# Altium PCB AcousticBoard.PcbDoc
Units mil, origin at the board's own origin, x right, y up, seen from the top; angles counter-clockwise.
Board outline 6000 x 4000 mil, 2 copper layers (Top Layer, Bottom Layer); 82 components, 63 nets, 281 pads, 66 vias.
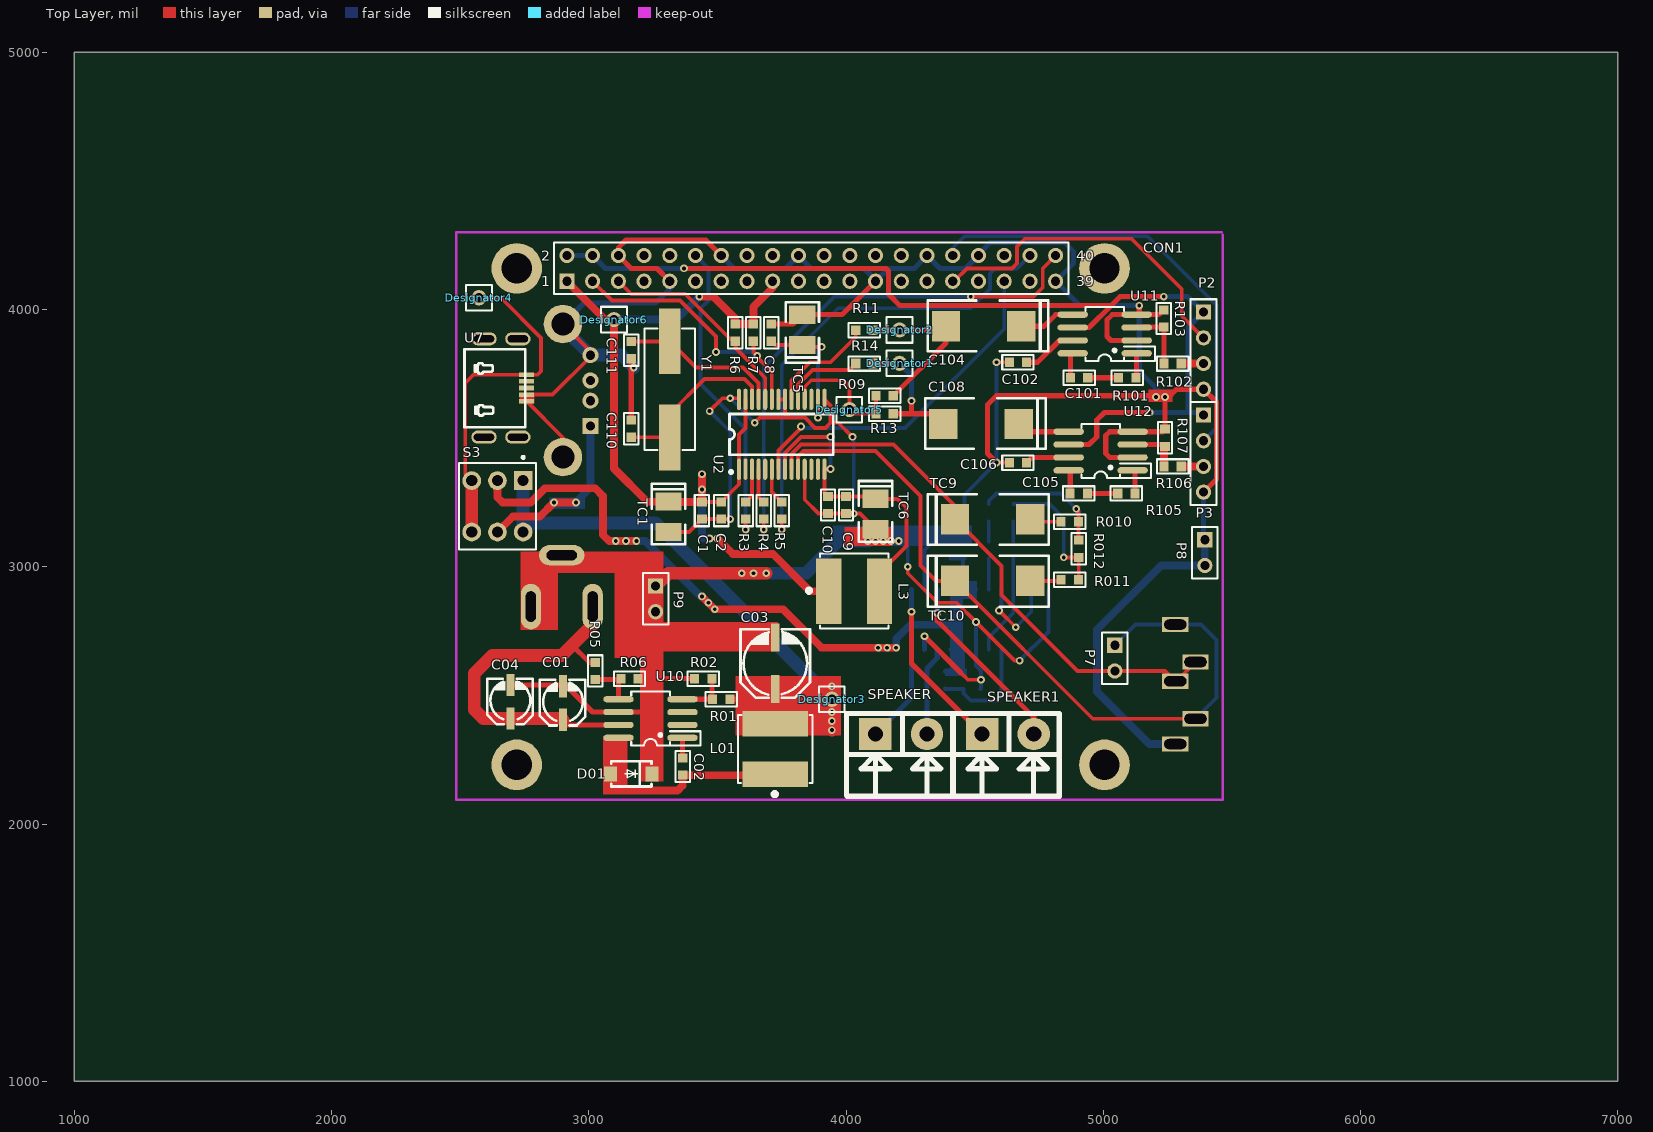
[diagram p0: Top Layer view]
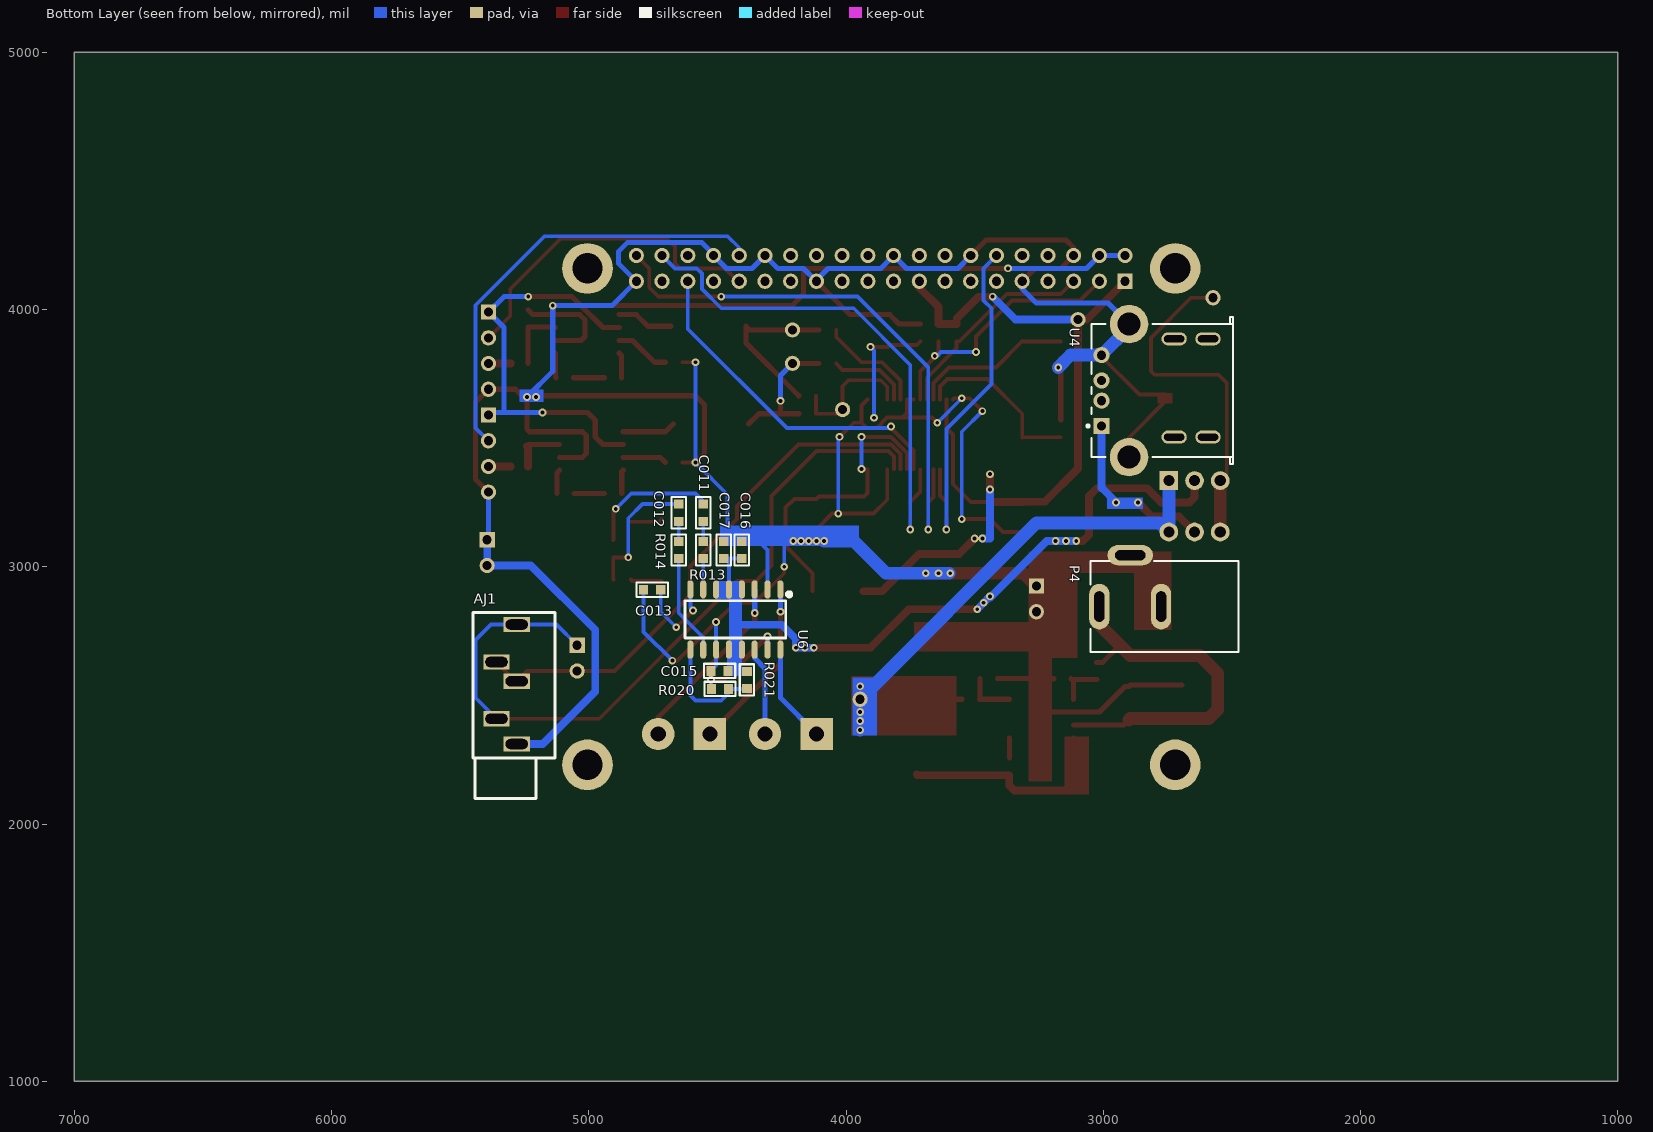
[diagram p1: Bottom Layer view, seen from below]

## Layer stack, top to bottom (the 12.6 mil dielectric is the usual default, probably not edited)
Top Solder: solder mask 0.4, Solder Resist, Dk 3.5
Top Layer: signal copper 1.4
Dielectric 1: dielectric 12.6, FR-4, Dk 4.8
Bottom Layer: signal copper 1.4
Bottom Solder: solder mask 0.4, Solder Resist, Dk 3.5

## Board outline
1000,1000 7000,1000 7000,5000 1000,5000

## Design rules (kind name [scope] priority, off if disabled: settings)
Clearance [All] p1: gap=5 ignorepadtopadclearanceinfootprint=FALSE
ComponentClearance [All] p1: gap=10 collisioncheckmode=3 verticalgap=6 showdistances=TRUE
PolygonConnect [All] p1: connectstyle=Relief reliefconductorwidth=10 reliefentries=4 polygonreliefangle="90 Angle" airgapwidth=10
RoutingVias [All] p1: holewidth=28 width=50 viastyle="Through Hole" minholewidth=10 minwidth=10 maxholewidth=50 maxwidth=100
SolderMaskExpansion [All] p1: expansion=4
Width [All] p1: maxlimit=100 minlimit=6 preferedwidth=50
29 further rules are at their usual default settings.

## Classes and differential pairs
component class MultiFcnAcousticBoard: AJ1 C1 C01 C02 C2 C03 C04 C8 C9 C10 C011 C012 C013 C015 C016 C017 C101 C102 C104 C105 C106 C108 C110 C111 CON1 D01 L01 L3 P2 P3 P4 P7 R01 R02 R3 R4 R5 R05 R6 R06 R7 R09 R010 R011 R012 R013 R13 R014 R020 R021 R101 R102 R103 R105 R106 R107 S3 SPEAKER SPEAKER1 TC1 TC5 TC6 TC9 TC10 U2 U4 U6 U7 U10 U11 U12 Y1

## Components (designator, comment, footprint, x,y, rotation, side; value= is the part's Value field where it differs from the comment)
AJ1 "AUDIOJACK" PJ-325C 5319.37,2543.18 r90 bottom
C01 "4.7uF" CAP-D4.0XH5.5 2900,2470 r270 top
C1 "0.1uF/0603" C0603 3440,3218.46 r90 top
C02 "10pF" C0603 3365,2223.46 r90 top
C2 "0.1uF/0603" C0603 3515,3218.46 r90 top
C03 "100uF" CAP-D6.3XH7.7 3725,2625 r270 top
C04 "4.7uF" CAP-D4.0XH5.5 2695,2475 r270 top
C8 "0.1uF/0603" C0603 3710,3910 r270 top
C9 "0.1uF/0603" C0603 4000,3240 r90 top
C10 "0.1uF/0603" C0603 3930,3240 r90 top
C011 "1uF" C0603 4555,3210 r90 bottom
C012 "1uF" C0603 4650,3210 r90 bottom
C013 "1uF" C0603 4753.46,2910 r0 bottom
C015 "0.1uF" C0603 4491.54,2595 r0 bottom
C016 "1uF" C0603 4405,3065 r90 bottom
C017 "1uF" C0603 4475,3065 r270 bottom
C101 "0.47uF" C0603 4906.54,3735 r0 top
C102 "0.1uF" C0603 4668.47,3795 r0 top
C104 "47uF" CASE-D_7343 4535,3935 r0 top
C105 "0.47uF" C0603 4905,3285 r0 top
C106 "0.1uF" C0603 4668.47,3405 r0 top
C108 "47uF" CASE-D_7343 4525,3555 r0 top
C110 "30pF/0603" C0603 3165,3537.01 r90 top
C111 "30pF/0603" C0603 3165,3842.01 r270 top
CON1 "RPI_40PIN_CON" HDR2X20 2915,4110 r0 top
D01 "B340A" SMA(DO-214AC) 3165,2195 r0 top
Designator1 "Comment" TP 4210,3790 r0 top
Designator2 "Comment" TP 4210,3920 r0 top
Designator3 "Comment" TP 3946.98,2484.16 r0 top
Designator4 "Comment" TP 2575,4045 r0 top
Designator5 "Comment" TP 4015,3610 r0 top
Designator6 "Comment" TP 3100,3960 r0 top
L01 "33uH" INDUCTOR 3725,2193.15 r90 top
L3 "10uH/1264EY-100M=P3" INDUCTOR 3933.15,2905 r0 top
P2 "Header 4" HDR1X4 5390,3990 r270 top
P3 "Header 4" HDR1X4 5390,3590 r270 top
P4 "Header 3" DC-005 3050,2845 r180 bottom
P7 "Header 2" HDR1X2 5045,2695 r270 top
P8 "Header 2" HDR1X2 5395,3105 r270 top (schematic designator P7)
P9 "Header 2" HDR1X2 3260,2925 r270 top (schematic designator P7)
R01 "10KΩ" R0603 3515,2485 r180 top
R02 "3.24KΩ" R0603 3445,2565 r180 top
R3 "27 ohm/0603" R0603 3610,3218.46 r270 top
R4 "1K/0603" R0603 3680,3218.46 r270 top
R05 "220KΩ" R0603 3025,2595 r270 top
R5 "27 ohm/0603" R0603 3750,3218.46 r270 top
R06 "20KΩ" R0603 3158.46,2565 r0 top
R6 "1K/0603" R0603 3570,3910 r90 top
R7 "1K/0603" R0603 3640,3910 r90 top
R09 "0/0603" R0603 4150,3665 r0 top
R010 "1KΩ" R0603 4870,3175 r180 top
R11 "0/0603" R0603 4071.53,3920 r0 top
R011 "1KΩ" R0603 4870,2950 r180 top
R012 "1KΩ" R0603 4905,3070 r270 top
R013 "1KΩ" R0603 4555,3065 r270 bottom
R13 "0/0603" R0603 4150,3595 r0 top
R14 "0/0603" R0603 4071.53,3790 r0 top
R014 "1KΩ" R0603 4650,3065 r270 bottom
R020 "" R0603 4490,2525 r0 bottom value=1KΩ
R021 "" R0603 4385,2560 r90 bottom value=1KΩ
R101 "10KΩ" R0603 5093.46,3735 r180 top
R102 "10KΩ" R0603 5270,3790 r0 top
R103 "10KΩ" R0603 5235,3965 r270 top
R105 "10KΩ" R0603 5090,3285 r180 top
R106 "10KΩ" R0603 5270,3390 r0 top
R107 "10KΩ" R0603 5240,3501.54 r270 top
S3 "SW-DPDT" DPDT-6 2645,3235 r270 top
SPEAKER "" SPEAKER 4200,2265 r90 top
SPEAKER1 "" SPEAKER 4615,2265 r90 top
TC1 "10uF/TAN/1206" CASE-B_3528 3310,3194.1 r90 top
TC5 "10uF/TAN/1206" CASE-B_3528 3830,3920.9 r270 top
TC6 "10uF/TAN/1206" CASE-B_3528 4115,3205 r90 top
TC9 "47uF" CASE-D_7343 4570,3185 r180 top
TC10 "47uF" CASE-D_7343 4570,2945 r180 top
U2 "WM8731SEDS/RV" SSOP-28_208MIL 3750,3515 r90 top
U4 "USB" USB_A1 2495,3685 r180 bottom
U6 "PAM8406(9号为MODE位)" SOIC-16_150MIL 4430,2795 r0 bottom
U7 "microUSB" MICRO-USB-A18 2675,3695 r180 top
U10 "TPS5420'" SOIC-8 3240,2410 r180 top
U11 "LM386" SOIC-8 5005.68,3905 r180 top
U12 "LM386" SOIC-8 4990,3450 r180 top
Y1 "XTAL" XTAL_SMD 3315,3690 r90 top

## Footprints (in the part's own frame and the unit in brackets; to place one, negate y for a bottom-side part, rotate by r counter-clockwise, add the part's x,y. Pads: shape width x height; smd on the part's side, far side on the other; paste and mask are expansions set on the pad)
C0603 [mm]
  rect 0.9x0.95 smd: 1(0.85,0) 2(-0.85,0)
  silkscreen extent -1.55,-0.71 1.55,0.71, body extent -0.85,-0.45 0.85,0.45, height 0.45
CAP-D4.0XH5.5 [mm]
  rect 2.2x0.8 smd: 1(1.651,0) 2(-1.651,0)
  silkscreen extent -2.29,-2.29 2.21,2.21
CAP-D6.3XH7.7 [mm]
  rect 2.8x0.8 smd: 1(2.54,0) 2(-2.54,0)
  silkscreen extent -3.37,-3.43 3.43,3.43
CASE-B_3528 [mm]
  rect 1.8x2.6 smd: 1(1.501,0) 2(-1.501,0)
  silkscreen extent -2.73,-1.65 3.26,1.65
CASE-D_7343 [mil]
  rect 110.2x118.5 smd: 1(146.5,0) 2(-146.5,0)
  silkscreen extent -218,-97 252,100
DC-005 [mm] "DC母座5.5mm"
  oval 2x4.5 hole 1 slot 3 at 90 deg: 1(0.889,0) 2(6.985,0)
  oval 4.5x2 hole 1 slot 3 at 0 deg: 3(3.937,5.08)
  silkscreen extent 0,-4.5 14.6,4.5, body extent 0,-4.45 14.6,4.44, height 11
DPDT-6 [mm] "Switch; 6 Leads"
  rect 1.85x1.85 hole 1.1: 1(-2.54,2.54)
  round 1.85 hole 1.1: 2(-2.54,0) 3(-2.54,-2.54) 4(2.54,-2.54) 5(2.54,0) 6(2.54,2.54)
  silkscreen extent -4.96,-3.81 4.28,3.81
HDR1X2 [mm] "Connector; Header; 2 Position"
  rect 1.5x1.5 hole 0.9: 1(0,0)
  round 1.5 hole 0.9: 2(2.54,0)
  silkscreen extent -1.27,-1.27 3.81,1.27
HDR1X4 [mm] "Connector; Header; 4 Position"
  rect 1.5x1.5 hole 0.9: 1(0,0)
  round 1.5 hole 0.9: 2(2.54,0) 3(5.08,0) 4(7.62,0)
  silkscreen extent -1.27,-1.27 8.89,1.27
HDR2X20 [mm] "Connector; Header; 20x2 Position"
  rect 1.5x1.5 hole 0.9: 1(0,0)
  round 1.5 hole 0.9: 2(0,2.54) 3(2.54,0) 4(2.54,2.54) 5(5.08,0) 6(5.08,2.54) 7(7.62,0) 8(7.62,2.54) 9(10.16,0) 10(10.16,2.54) 11(12.7,0) 12(12.7,2.54) 13(15.24,0) 14(15.24,2.54) 15(17.78,0) 16(17.78,2.54) 17(20.32,0) 18(20.32,2.54) 19(22.86,0) 20(22.86,2.54) 21(25.4,0) 22(25.4,2.54) 23(27.94,0) 24(27.94,2.54) 25(30.48,0) 26(30.48,2.54) 27(33.02,0) 28(33.02,2.54) 29(35.56,0) 30(35.56,2.54) 31(38.1,0) 32(38.1,2.54) 33(40.64,0) 34(40.64,2.54) 35(43.18,0) 36(43.18,2.54) 37(45.72,0) 38(45.72,2.54) 39(48.26,0) 40(48.26,2.54)
  silkscreen extent -1.27,-1.27 49.53,3.81
INDUCTOR [mm]
  rect 2.5x6.5 smd: 1(0,0) 2(5,0)
  silkscreen extent -2.11,-3.7 5.88,3.7
MICRO-USB-A18 [mm]
  oval 2.5x1.3 hole 0.7 slot 2 at 0 deg: 0(-1.256,4.849) 0(-1.256,-4.849) 0(2.095,4.849) 0(2.095,-4.849)
  rect 1.5x0.45 smd: 1(-2.094,-1.301) 2(-2.094,-0.651) 3(-2.094,-0.001) 4(-2.094,0.65) 5(-2.094,1.3)
  silkscreen extent -1.98,-3.84 4.02,3.86
PJ-325C [mm]
  rect 1.5x2.597 hole 1 slot 2.2 at 90 deg: 1(-5.9,-1) 2(-3.4,1) 3(2.2,1) 10(5.9,-1) 11(0.3,-1)
  silkscreen extent -11.3,-4.8 7.1,3.3
R0603 [mm]
  rect 0.9x0.95 smd: 1(0.85,0) 2(-0.85,0)
  silkscreen extent -1.55,-0.71 1.55,0.71, body extent -0.85,-0.45 0.85,0.45, height 0.45
SMA(DO-214AC) [mil]
  rect 50x57.9 smd: 1(-81,0) 2(81,0)
  silkscreen extent -78,-49 79,49
SOIC-8 [mil] "SOIC, 8-Leads, Body 5.0x4.0mm (max), Pitch 1.27mm, IPC Medium Density"
  oval 118.11x24 smd: 1(-124.31,75) 2(-124.31,25) 3(-124.31,-25) 4(-124.31,-75) 5(124.32,-75) 6(124.32,-25) 7(124.32,25) 8(124.32,75)
  silkscreen extent -195,-104 75,104, body extent -75,-99 75,101, height 69
SOIC-16_150MIL [mm]
  oval 0.6x1.8 smd: 1(-4.445,-2.972) 2(-3.175,-2.972) 3(-1.905,-2.972) 4(-0.635,-2.972) 5(0.635,-2.972) 6(1.905,-2.972) 7(3.175,-2.972) 8(4.445,-2.972) 9(4.445,2.972) 10(3.175,2.972) 11(1.905,2.972) 12(0.635,2.972) 13(-0.635,2.972) 14(-1.905,2.972) 15(-3.175,2.972) 16(-4.445,2.972)
  silkscreen extent -5.51,-2.69 4.98,1.83
SPEAKER [mm]
  rect 3.2x3.2 hole 1.5: 1(2.159,2.179)
  round 3.2 hole 1.5: 2(2.159,-2.921)
  silkscreen extent -3.99,-5.46 4.19,5.03
SSOP-28_208MIL [mm]
  oval 2.1x0.4 smd: 1(-3.45,4.225) 2(-3.45,3.575) 3(-3.45,2.925) 4(-3.45,2.275) 5(-3.45,1.625) 6(-3.45,0.975) 7(-3.45,0.325) 8(-3.45,-0.325) 9(-3.45,-0.975) 10(-3.45,-1.625) 11(-3.45,-2.275) 12(-3.45,-2.925) 13(-3.45,-3.575) 14(-3.45,-4.225) 15(3.45,-4.225) 16(3.45,-3.575) 17(3.45,-2.925) 18(3.45,-2.275) 19(3.45,-1.625) 20(3.45,-0.975) 21(3.45,-0.325) 22(3.45,0.325) 23(3.45,0.975) 24(3.45,1.625) 25(3.45,2.275) 26(3.45,2.925) 27(3.45,3.575) 28(3.45,4.225)
  silkscreen extent -3.87,-5.1 2,5.15
TP [mm]
  round 1.5 hole 0.9: 1(-0.05,0.021)
  silkscreen extent -1.32,-1.25 1.22,1.29
USB_A1 [mm]
  rect 1.6x1.6 hole 0.92: 1(-12.99,-3.5)
  round 1.6 hole 0.92: 2(-12.99,-1) 3(-12.99,1) 4(-12.99,3.5)
  round 3.8 hole 2.3: 5(-10.28,6.57) 6(-10.28,-6.57)
  silkscreen extent -14.47,-7.25 0,7.25
XTAL_SMD [mm]
  rect 6.5x2.1 smd: 1(-4.75,0) 2(4.75,0)
  silkscreen extent -6,-2.5 6,2.5

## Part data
C01 C1 C02 C2 C04 C8 C9 C10 C011 C012 C013 C015 C016 C017 C101 C102 C104 C105 C106 C108 C110 C111: library part C
C03: library part Cap2, "Capacitor"
D01: library part "Diode 10TQ040", "Schottky Rectifier"
L01: library part "Inductor Iron Dot", "Magnetic-Core Inductor with Winding Polarity Marking"
L3: library part L
P2 P3: "Header, 4-Pin"
P4: "Header, 3-Pin"
P7 P8 P9: "Header, 2-Pin"
R01 R02 R3 R4 R05 R5 R06 R6 R7 R09 R010 R11 R011 R012 R013 R13 R14 R014 R101 R102 R103 R105 R106 R107: library part RES
R020 R021: library part Res3, "Resistor"
S3: "Double-Pole, Double-Throw Switch"
SPEAKER SPEAKER1: library part SPEAKER
TC1 TC5 TC6 TC9 TC10: library part TAN_C
U2: library part XWM8731EDS
U6: library part PAM8403, "PAM8403"
Y1: "Crystal Oscillator"

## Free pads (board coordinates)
  round 196.85 hole 118.11: 0(5005,4160) 1(2720,4160) 2(2720,2230) 2(5005,2230)

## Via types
v1: diameter 30, hole 15, Top Layer to Bottom Layer, 66 vias

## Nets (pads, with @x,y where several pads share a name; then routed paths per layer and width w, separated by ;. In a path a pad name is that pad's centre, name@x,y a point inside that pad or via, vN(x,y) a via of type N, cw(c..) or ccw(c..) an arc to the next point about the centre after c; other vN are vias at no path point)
3V3: C1.1 C2.1 CON1.1 CON1.17 Designator6.1 L3.1 R6.1 R7.1 TC1.1 U2.1 U2.27 | length 3411.8
  Top Layer w15: C1.1 C2.1 3583.66,3320.59 U2.1 3583.66,3513.66 3609.25,3539.25 U2.27
  Top Layer w30: CON1.1 3064.16,3960.84 Designator6.1 3098.02,3381.98 3226.8,3253.2 TC1.1 3311.27,3251.93 C1.1 v1(3440,3300) v1(3440,3360) ; v1(3430,4050) 3485,4050 3570,3965 R6.1 R7.1 3640,4010 3715,4085 CON1.17 ; v1(3500,3110) 3560,3050 3715,3050 3860,2905 L3.1
  Bottom Layer w30: Designator6.1 3340.84,3960.84 v1(3430,4050) ; v1(3440,3300) 3440,3110 v1(3470,3110)
5V: CON1.2 CON1.4 P2.1 P3.1 U11.6 U12.6 | length 3864.8
  Top Layer w20: v1(3370,4160) 4155,4160 4165,4150 4165,4060 4210,4015 5030,4015 ; U12.6 4945,3475 4975,3505 4975,3570 5005,3600 v1(5180,3600) ; U11.6 4945,3930 5030,4015 ; v1(5235,4050) 5065,4050 5030,4015
  Bottom Layer w20: CON1.2 CON1.4 3065,4160 v1(3370,4160) ; v1(5180,3600) 5330,3600 ; v1(5235,4050) 5330,4050 P2.1 5330,3930 5330,3600 ; P3.1 5380,3600 5330,3600
+12: 
ACD_MISO: CON1.38 R5.1 | length 1856.2
  Top Layer w15: v1(3750,3145) R5.1
  Bottom Layer w15: v1(3750,3145) 3750,3785 3970,4005 4485,4005 4560,4080 4560,4140 4580,4160 4665,4160 CON1.38
ACD_MOSI: CON1.40 R4.1 | length 2029.1
  Top Layer w15: v1(3680,3145) R4.1 ; v1(4485,4050) 4730,4050 4765,4085 4765,4160 CON1.40
  Bottom Layer w15: v1(3680,3145) 3680,3775 3955,4050 v1(4485,4050)
ACD_SCK: CON1.12 R3.1 | length 1210.6
  Top Layer w15: v1(3610,3145) R3.1
  Bottom Layer w15: CON1.12 3465,4160 3465,4035 3435,4005 3435,3710 3610,3535 v1(3610,3145)
ADCLRC: CON1.35 U2.7 | length 1341.7
  Top Layer w15: U2.7 3737.2,3452.2 3825,3540 v1(3825,3545)
  Bottom Layer w15: v1(3825,3545) 3825,3540 4230,3540 4615,3925 CON1.35
AP: C015.2 C016.2 C017.1 R021.1 S3.2 U6.4 U6.5 U6.6 U6.12 U6.13 | length 3006.3
  Top Layer w30: S3.2 2645,3270 2665,3250 2775,3250 2830,3305 3025,3305 3055,3275 3055,3125 3080,3100 v1(3105,3100) v1(3145,3100) v1(3185,3100) ; v1@3445,2880 v1(3465,2860) v1(3490,2835) 3755,2835 3905,2685 v1(4125,2685) v1(4160,2685) v1(4195,2685)
  Bottom Layer w15: R021.1 4386.54,2595 C015.2 4455,2598.07 U6.12 U6.13 ; U6.4 U6.5 ; C016.2 4460,3031.53 4455,3026.53 U6.5 ; U6.6 U6.5
  Bottom Layer w30: v1@3110,3100 v1(3145,3100) v1(3185,3100) 3220,3100 3440,2880 v1(3440,2885) v1(3465,2860) v1(3490,2835) ; v1(4125,2685) v1(4160,2685) v1(4195,2685) 4195,2720 4250,2775 4410,2775 4440,2745
BAT_IN: C01.1 C04.1 P4.1 R05.2 U10.7 | length 1451.8
  Top Layer w20: C01.1 2920,2385 U10.7 ; 2935,2695 3001.54,2628.46 R05.2
  Top Layer w50: C01.1 2895,2410 C04.1 2590,2410 2555,2445 2555,2585 2625,2655 2895,2655 2935,2695 3015,2775 P4.1
CTRL1: CON1.31 P2.2 | length 1302.4
  Top Layer w15: CON1.31 4420,4110 4470,4160 4645,4160 4665,4180 4665,4245 4695,4275 5110,4275 5305,4080 5305,3975 P2.2
CTRL2: CON1.32 P3.2 | length 1732.2
  Bottom Layer w15: CON1.32 4415,4240 4460,4285 5171.73,4285 5440,4016.73 5440,3540 P3.2
GND: AJ1.1 C1.2 C01.2 C2.2 C03.2 C04.2 C8.2 C9.2 C10.2 C013.1 C015.1 C016.1 C017.2 C102.2 C106.2 C110.1 C111.1 CON1.6 CON1.9 CON1.14 CON1.20 CON1.25 CON1.30 CON1.34 CON1.39 D01.2 P2.4 P3.4 P4.2 P4.3 P8.1 P8.2 P9.1 P9.2 R02.1 R06.1 R020.1 R103.2 R107.2 TC1.2 TC5.2 TC6.2 U2.11 U2.15 U2.21 U2.22 U2.28 U4.4 U4.5 U4.6 U6.2 U6.11 U6.15 U7.4 U7.5 U10.6 U11.2 U11.4 U12.2 U12.4 | length 17049.5
  Top Layer w15: U7.5 2899.72,3501.56 U4.6 ; U7.4 2859.42,3669.42 3006.42,3816.42 U4.4 3006.42,3836.97 U4.5 ; TC1.2 3390,3135 C1.2 C2.2 v1(3550,3185) ; v1(3470,3605) 3520,3655 v1(3550,3655) 3579.49,3655 U2.28 ; v1(3645,3560) 3665,3580 3780,3580 ; U2.22 U2.21 3762.8,3597.2 3780,3580 ; U2.11 3839.57,3260.43 3893.46,3206.54 C10.2 C9.2 v1(4030,3206.54) 4054.36,3206.54 TC6.2 v1(4115,3100) ; U2.15 3940,3627.17 3940,3560 ; v1(4025,3505) 3970,3560 3940,3560 ; v1(4240,3000) 4240,2975 4355,2860 4430,2860 v1(4505,2785) 4655,2635 v1(4675,2635) ; 4447.5,2587.5 4474.23,2560.77 v1(4525,2560.77) ; v1(4585,3405) C106.2 ; v1(4585,3795) C102.2 ; 3780,3580 3840,3580 3880,3540 3920,3540 3940,3560
  Top Layer w20: C04.2 2895,2540 C01.2 2915,2535 3015,2435 U10.6 3246,2435 ; C110.1 v1@3165,3785 ; C111.1 v1@3165,3785 ; v1(3175,3775) v1@3165,3785 ; D01.2 3246,2435 ; CON1.9 3265,4160 3165,4160 CON1.6 3115,4240 3145,4270 3455,4270 CON1.14 ; R02.1 R06.1 3192.93,2564 3246,2564 3246,2435 ; C8.2 3793.47,3943.47 TC5.2 3985,3980 CON1.25 ; v1(4305,2730) 4447.5,2587.5 ; v1(4585,3405) 4550,3440 4550,3630 4585,3665 v1@5205,3665 ; U12.2 5025,3425 5010,3440 5010,3510 5025,3525 U12.4 5230,3525 R107.2 5240,3645 ; U11.2 5030,3880 5015,3895 5015,3960 5035,3980 U11.4 ; v1(5140,4015) 5140,3990 U11.4 ; R103.2 5216.54,3980 U11.4 ; v1@5247.5,3652.5 5285,3690 P2.4 5440,3640 5440,3340 P3.4
  Top Layer w50: P9.1 3310,2975 v1(3595,2975) v1(3640,2975) v1(3690,2975)
  Bottom Layer w10: v1(4085,3100) v1(4115,3100) v1(4145,3100) v1(4175,3100) v1(4205,3100)
  Bottom Layer w15: v1(3470,3605) 3550,3525 v1(3550,3185) ; v1(3550,3655) v1(3645,3560) ; v1(4025,3505) 4030,3500 v1(4030,3206.54) ; v1(4240,3000) 4240,3095 ; U6.2 4305,3065 4338.46,3098.46 C016.1 C017.2 ; 4460,3125 4460,3280 v1(4585,3405) v1(4585,3795) ; v1(4505,2785) U6.11 4505,2615 C015.1 v1(4525,2560.77) 4525,2526.54 R020.1 ; v1(4675,2635) 4786.93,2746.93 C013.1
  Bottom Layer w20: U4.5 2981.06,4025 3260,4025 3315,4080 CON1.9 ; CON1.14 3565,4160 3765,4160 CON1.20 3865,4160 4070,4160 4115,4115 CON1.25 4165,4160 4265,4160 CON1.30 4365,4160 4465,4160 CON1.34 4515,4215 4560,4260 4850,4260 4885,4225 4885,4180 CON1.39 4910,4015 v1(5140,4015) 5140,3760 v1(5240,3660) v1(5205,3660) ; U6.15 v1(4305,2730) ; P3.4 5390,3110 P8.1
  Bottom Layer w30: AJ1.1 5179.1,2310.9 4975,2515 4975,2755 5225,3005 P8.2 P8.1
  Bottom Layer w50: U4.5 2899.72,3929.49 U4.4 3127.2,3822.8 v1(3175,3775) ; v1@3600,2975 v1(3640,2975) v1(3690,2975) 3845,2975 3970,3100 v1(4085,3100)
I2C_SCL: CON1.5 R6.2 U2.24 | length 825.5
  Top Layer w15: CON1.5 3165,4060 3375,4060 3558.46,3876.54 R6.2 3570,3850 3686.02,3733.98 U2.24
I2C_SDA: CON1.3 R7.2 U2.23 | length 1049.2
  Top Layer w15: CON1.3 3090,4035 3355,4035 3495,3895 v1(3495,3835) ; R7.2 3640,3835 v1(3655,3820) ; v1@3652.5,3817.5 3711.61,3758.39 U2.23
  Bottom Layer w15: v1(3495,3835) 3630,3835 3645,3820 v1(3655,3820)
IN5V: S3.5 U4.1 | length 708.2
  Top Layer w30: S3.5 2705,3195 2810,3195 v1(2865,3250) v1(2950,3250)
  Bottom Layer w30: v1(2865,3250) 2900,3250 ; v1(2950,3250) 3006.42,3306.42 U4.1
INPUT1: P2.3 R102.1 | length 86.5
  Top Layer w30: R102.1 P2.3
INPUT2: P3.3 R106.1 | length 86.5
  Top Layer w30: R106.1 P3.3
LLIN: R11.2 U2.20 | length 419.5
  Top Layer w15: U2.20 3788.39,3723.39 3860,3795 3940,3795 4038.07,3893.07 R11.2
LPOUT: AJ1.3 AJ1.11 P7.2 TC9.1 U2.9 | length 2153.4
  Top Layer w15: U2.9 3788.39,3438.39 3825,3475 4185,3475 4423.5,3236.5 TC9.1 4605,3003.5 4605,2890 4900,2595 P7.2 5240,2595 AJ1.11 5283.94,2555 AJ1.3
MICIN: Designator5.1 R09.2 R13.2 U2.18 | length 513.5
  Top Layer w15: U2.18 3839.57,3699.57 3865,3725 3990,3725 4013.02,3701.98 Designator5.1 4028.86,3595 R13.2 R09.2
NetC02_1: C02.1 U10.1 | length 78.4
  Top Layer w20: U10.1 3365,2334.31 C02.1
NetC02_2: C02.2 D01.1 L01.1 U10.8 | length 870.6
  Top Layer w20: D01.1 3115.68,2226.68 U10.8
  Top Layer w30: D01.1 3149,2130 3345,2130 3365,2150 C02.2 3721.85,2190 L01.1
NetC8_1: C8.1 TC5.1 U2.16 | length 557.2
  Top Layer w15: C8.1 3724.74,3861.8 TC5.1 3836.8,3855 v1(3905,3855) ; v1(3890.75,3579.25) U2.16
  Bottom Layer w15: v1(3890.75,3579.25) 3890.75,3840.75 v1(3905,3855)
NetC9_1: C9.1 C10.1 L3.2 TC6.1 U2.8 U2.14 | length 1218.5
  Top Layer w15: U2.8 3762.8,3442.8 3825,3505 v1(3940,3505) ; v1(3940,3380) 3939.17,3379.17 U2.14 3916.34,3287.12 C10.1 C9.1 4105.64,3273.46 TC6.1 4200.9,3264.1 4235,3230 4235,3080 4130,2975 L3.2
  Bottom Layer w15: v1(3940,3380) v1(3940,3505)
NetC011_1: C011.1 R010.2 R012.2 | length 514.5
  Top Layer w15: v1(4895,3225) 4903.46,3216.54 R010.2 4903.46,3105 R012.2
  Bottom Layer w15: C011.1 4555,3255 4585,3285 4835,3285 v1(4895,3225)
NetC011_2: C011.2 R013.2 | length 78.1
  Bottom Layer w15: R013.2 C011.2
NetC012_1: C012.1 R011.2 R012.1 | length 516.9
  Top Layer w15: v1(4846.54,3036.54) R012.1 4905,2951.54 R011.2
  Bottom Layer w15: C012.1 4791.54,3243.46 4846.54,3188.46 v1(4846.54,3036.54)
NetC012_2: C012.2 R014.2 | length 78.1
  Bottom Layer w15: R014.2 C012.2
NetC013_2: C013.2 U6.8 | length 347.9
  Top Layer w15: v1(4595,2830) v1(4660,2765)
  Bottom Layer w15: v1(4595,2830) 4605,2840 U6.8 ; v1(4660,2765) 4720,2825 C013.2
NetC101_1: C101.1 R101.1 | length 120
  Top Layer w20: C101.1 R101.1
NetC101_2: C101.2 U11.8 | length 98.4
  Top Layer w20: C101.2 4873.07,3821.7 U11.8
NetC102_1: C102.1 U11.7 | length 214.6
  Top Layer w20: C102.1 4745,3795 4830,3880 U11.7
NetC104_1: C104.2 Designator2.1 R09.1 R11.1 | length 644.6
  Top Layer w20: R11.1 4105.84,3920.84 Designator2.1 4374.34,3920.84 C104.2 4388.5,3870.04 R09.1
NetC104_2: C104.1 U11.5 | length 218.5
  Top Layer w20: C104.1 4770,3935 4815,3980 U11.5
NetC105_1: C105.1 R105.1 | length 118.1
  Top Layer w20: C105.1 R105.1
NetC105_2: C105.2 U12.8 | length 92.4
  Top Layer w20: U12.8 4871.53,3369.15 C105.2
NetC106_1: C106.1 U12.7 | length 172
  Top Layer w20: C106.1 4721.93,3425 U12.7
NetC108_1: C108.2 Designator1.1 R13.1 R14.1 | length 532.3
  Top Layer w20: R14.1 4207.18,3790 Designator1.1 ; R13.1 4250,3595 ; v1(4255,3645) 4255,3600 4250,3595 ; C108.2 4338.5,3595 4250,3595
  Bottom Layer w20: Designator1.1 4255,3743.86 v1(4255,3645)
NetC108_2: C108.1 U12.5 | length 206.6
  Top Layer w20: C108.1 4701.5,3525 U12.5
NetC110_2: C110.2 U2.26 Y1.1 | length 679.7
  Top Layer w15: C110.2 3314.45,3503.54 Y1.1 3315,3595 3450,3730 3605,3730 3634.84,3700.16 U2.26
NetC111_2: C111.2 U2.25 Y1.2 | length 627.1
  Top Layer w15: C111.2 3313.46,3875.47 Y1.2 3417.01,3775 3600,3775 3660.43,3714.57 U2.25
NetR01_1: R01.1 R02.2 U10.4 | length 198.5
  Top Layer w20: U10.4 R01.1 3478.46,2488.07 R02.2
NetR3_2: R3.2 U2.3 | length 137.5
  Top Layer w15: R3.2 3634.84,3276.77 U2.3
NetR4_2: R4.2 U2.4 | length 135.3
  Top Layer w15: U2.4 3660.43,3271.5 R4.2
NetR05_1: R05.1 R06.2 U10.5 | length 180.4
  Top Layer w20: R05.1 R06.2@3121.54,2561.54 ; U10.5 3115.68,2555.68 R06.2@3121.54,2561.54 ; R06.2 R06.2@3121.54,2561.54
NetR5_2: R5.2 U2.6 | length 143.1
  Top Layer w15: U2.6 3711.61,3290.32 R5.2
NetR010_1: R010.1 TC9.2 | length 124.2
  Top Layer w15: TC9.2 4726.5,3175 R010.1
NetR011_1: R011.1 TC10.2 | length 122.1
  Top Layer w15: TC10.2 4831.53,2945 R011.1
NetR013_1: R013.1 U6.7 | length 119.5
  Bottom Layer w15: U6.7 R013.1
NetR014_1: R014.1 U6.10 | length 392.9
  Bottom Layer w15: U6.10 4555,2725 4650,2820 R014.1
NetR020_2: R020.2 R021.2 U6.9 | length 435.2
  Bottom Layer w15: R021.2 4386.54,2525 R020.2 4456.53,2508.47 4485,2480 4585,2480 4605,2500 U6.9
NetR101_2: R101.2 U11.1 | length 96.3
  Top Layer w20: R101.2 5130,3738.07 U11.1
NetR102_2: R102.2 R103.1 U11.3 | length 247.8
  Top Layer w20: U11.3 5131.54,3931.54 R103.1 5236.53,3930 R102.2
NetR105_2: R105.2 U12.1 | length 93.8
  Top Layer w20: U12.1 5123.46,3365.85 R105.2
NetR106_2: R106.2 R107.1 U12.3 | length 208.1
  Top Layer w20: U12.3 5233.07,3475 R107.1
  Top Layer w30: R106.2 5236.54,3464.61 R107.1
NetSPEAKER1_1: SPEAKER1.1 U6.1 | length 675.6
  Top Layer w20: v1(4255,2825) 4255,2624.21 SPEAKER1.1
  Bottom Layer w20: v1(4255,2825) U6.1
NetSPEAKER1_2: SPEAKER1.2 U6.3 | length 717.3
  Top Layer w20: v1(4355,2820) 4355,2790 4730,2415 SPEAKER1.2
  Bottom Layer w20: v1(4355,2820) U6.3
NetSPEAKER_1: SPEAKER.2 U6.14 | length 344.6
  Bottom Layer w20: SPEAKER.2 4315,2605 4355,2645 U6.14
NetSPEAKER_2: SPEAKER.1 U6.16 | length 386.3
  Bottom Layer w20: SPEAKER.1 4255,2490.79 U6.16
RLIN: R14.2 U2.19 | length 315.8
  Top Layer w15: U2.19 3813.98,3708.98 3870,3765 4013.07,3765 R14.2
RPOUT: AJ1.2 AJ1.10 P7.1 TC10.1 U2.10 | length 2985.2
  Top Layer w15: U2.10 3813.98,3428.98 3835,3450 4115,3450 4290,3275 4290,3005 4350,2945 TC10.1 4959.17,2409.33 AJ1.2
  Bottom Layer w15: P7.1 5125.47,2775.47 AJ1.10 5379.53,2775.47 5440,2715 5440,2490.59 AJ1.2
VBUS: Designator4.1 S3.3 S3.4 U7.1 | length 1340.5
  Top Layer w15: S3.3 2520,3360 2520,3715 2551.22,3746.22 U7.1 2801.22,3746.22 2815,3760 2815,3890 2659.16,4045.84 Designator4.1
  Top Layer w50: S3.4 S3.3
VCC_5V: C03.1 Designator3.1 L01.2 R01.2 S3.1 S3.6 | length 2574.1
  Top Layer w20: R01.2 3630,2485 L01.2 C03.1@3725,2470 ; C03.1 C03.1@3725,2470 ; 3760,2485 3760,2470 C03.1@3725,2470
  Top Layer w50: 3760,2485 Designator3.1 ; v1(3945,2365) v1(3945,2400) v1(3945,2435) Designator3.1 ; v1(3945,2535) Designator3.1
  Bottom Layer w50: S3.1 S3.6 2780,3170 3260,3170 Designator3.1 v1(3945,2435) v1(3945,2400) v1(3945,2365)
pads on no net: CON1.7 CON1.8 CON1.10 CON1.11 CON1.13 CON1.15 CON1.16 CON1.18 CON1.19 CON1.21 CON1.22 CON1.23 CON1.24 CON1.26 CON1.27 CON1.28 CON1.29 CON1.33 CON1.36 CON1.37 U2.2 U2.5 U2.12 U2.13 U2.17 U4.2 U4.3 U7.0 U7.2 U7.3 U10.2 U10.3

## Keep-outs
Top Layer:
  lines w10: 5460,4300 2485,4300 2485,2095 5465,2095 5465,4290

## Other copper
Top Layer:
  rectangle net GND: 2730,3635 2790,3675
  rectangle net GND: 5175,3640 5270,3690
  rectangle net GND: 3995,3080 4180,3155
  rectangle net VCC_5V: 3855,2345 3980,2575
  rectangle net NetC02_2: 3055,2115 3150,2340
  rectangle net VCC_5V: 3570,2345 3855,2575
  rectangle net GND: 3245,2670 3735,2785
  rectangle net GND: 3100,2645 3270,3000
  rectangle net GND: 2735,2755 2880,3040
  rectangle net GND: 2735,2975 3290,3060
  rectangle net GND: 3200,2165 3290,2995
Bottom Layer:
  rectangle net GND: 5175,3640 5270,3690
  rectangle net GND: 3950,3080 4490,3160
  rectangle net AP: 4430,2875 4510,2945
  rectangle net AP: 4385,2575 4470,2605
  rectangle net AP: 4405,2580 4455,2945
  rectangle net IN5V: 2845,3225 2985,3270
  rectangle net VCC_5V: 3880,2345 3975,2570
